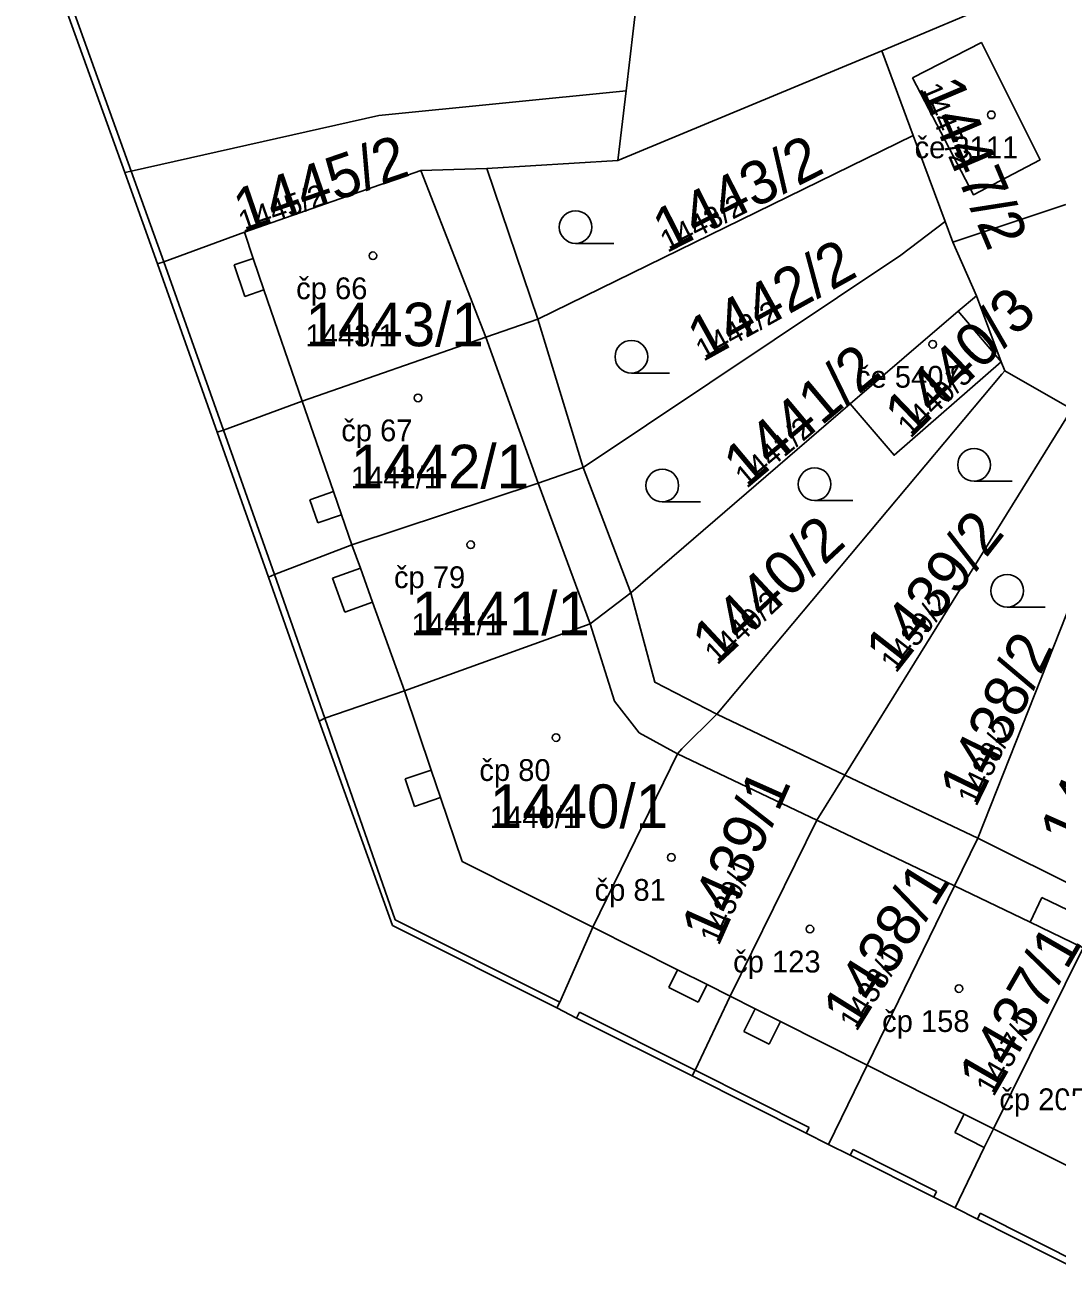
# Model space of a CAD drawing. Extents: x -763628 to -761565, y -976033 to -973833.
# Drawn here: x -762801.6 to -762754.2, y -975864.2 to -975806.8 of the extents above; entities that cross this region are included whole.
import ezdxf

# ---------------------------------------------------------------- set-up
doc = ezdxf.new("R2010")
doc.units = 0
for name, color, linetype in [('KN_cisla parcel 1000', 7, 'Continuous'), ('KN_cisla parcel 500', 7, 'Continuous'), ('KN_cisla popisna 500', 7, 'Continuous'), ('KN_hranice parcel', 7, 'Continuous'), ('KN_hranice uzemi', 7, 'Continuous'), ('KN_vnitrni kresba parcel', 7, 'Continuous'), ('KN_znacky budov', 7, 'Continuous'), ('KN_znacky kultur', 7, 'Continuous')]:
    doc.layers.add(name, color=color, linetype=linetype)

msp = doc.modelspace()

# ---------------------------------------------------------------- linework, layer by layer
at = {"layer": 'KN_hranice parcel'}
for p, q in [((-762774.01, -975809.85), (-762768.82, -975765.48)), ((-762762.28, -975808.02), (-762743.75, -975800.22)), ((-762762.28, -975808.02), (-762774.39, -975813.06)), ((-762760.84, -975811.91), (-762762.28, -975808.02)), ((-762774.39, -975813.06), (-762774.01, -975809.85)), ((-762760.84, -975811.91), (-762778.06, -975820.34)), ((-762759.37, -975815.85), (-762760.84, -975811.91)), ((-762774.39, -975813.06), (-762780.41, -975813.42)), ((-762778.06, -975820.34), (-762780.41, -975813.42)), ((-762759.02, -975816.8), (-762753.83, -975815.07)), ((-762759.02, -975816.8), (-762759.37, -975815.85)), ((-762757.93, -975819.27), (-762759.02, -975816.8)), ((-762756.79, -975822.3), (-762757.93, -975819.27)), ((-762775.98, -975827.14), (-762778.06, -975820.34)), ((-762756.63, -975822.71), (-762756.79, -975822.3)), ((-762753.55, -975824.46), (-762756.63, -975822.71)), ((-762763.73, -975824.23), (-762773.79, -975832.9)), ((-762753.55, -975824.46), (-762763.97, -975841.26)), ((-762757.87, -975844.15), (-762750.65, -975825.91)), ((-762773.79, -975832.9), (-762775.98, -975827.14)), ((-762763.97, -975841.26), (-762769.85, -975838.47)), ((-762757.87, -975844.15), (-762763.97, -975841.26)), ((-762752.01, -975847.08), (-762757.87, -975844.15))]:
    msp.add_line(p, q, dxfattribs=at)
for points in [[(-762760.87, -975809.26), (-762758.07, -975814.63), (-762755.01, -975813.02), (-762757.7, -975807.64), (-762760.87, -975809.26)], [(-762797.02, -975813.61), (-762796.74, -975813.55), (-762785.37, -975810.99), (-762774.01, -975809.85)], [(-762780.41, -975813.42), (-762783.44, -975813.52), (-762791.54, -975816.34), (-762795.23, -975817.7), (-762795.52, -975817.8)], [(-762759.37, -975815.85), (-762761.41, -975817.4), (-762775.98, -975827.14)], [(-762757.93, -975819.27), (-762758.77, -975819.97), (-762763.73, -975824.23)], [(-762778.06, -975820.34), (-762780.45, -975821.16), (-762788.89, -975824.1), (-762792.5, -975825.43), (-762792.79, -975825.53)], [(-762756.63, -975822.71), (-762756.77, -975822.86), (-762769.85, -975838.47)], [(-762756.79, -975822.3), (-762761.71, -975826.58), (-762763.73, -975824.23)], [(-762775.98, -975827.14), (-762778.05, -975827.87), (-762786.6, -975830.7), (-762790.16, -975832.05), (-762790.43, -975832.18)], [(-762773.79, -975832.9), (-762775.67, -975834.32), (-762784.19, -975837.39), (-762787.84, -975838.65), (-762788.11, -975838.79)], [(-762769.85, -975838.47), (-762772.69, -975837), (-762773.79, -975832.9)], [(-762769.85, -975838.47), (-762771.46, -975840.06), (-762771.65, -975840.28), (-762775.54, -975848.24), (-762777.06, -975851.69), (-762777.2, -975851.95)], [(-762763.97, -975841.26), (-762765.26, -975843.33), (-762769.24, -975851.41), (-762770.85, -975854.8), (-762770.98, -975855.07)], [(-762757.87, -975844.15), (-762758.94, -975846.35), (-762762.95, -975854.57), (-762764.72, -975858.22)], [(-762752.01, -975847.08), (-762752.49, -975848.06), (-762753.03, -975849.19), (-762757.15, -975857.49), (-762757.58, -975858.35), (-762758.91, -975861.13)]]:
    msp.add_lwpolyline(points, dxfattribs=at)
at = {"layer": 'KN_hranice uzemi'}
for p, q in [((-762797.02, -975813.61), (-762801.61, -975800.86)), ((-762792.79, -975825.53), (-762795.52, -975817.8)), ((-762790.43, -975832.18), (-762792.79, -975825.53)), ((-762788.11, -975838.79), (-762790.43, -975832.18)), ((-762784.74, -975848.17), (-762788.11, -975838.79)), ((-762777.2, -975851.95), (-762784.74, -975848.17))]:
    msp.add_line(p, q, dxfattribs=at)
for points in [[(-762795.52, -975817.8), (-762796.87, -975814.04), (-762797.02, -975813.61)], [(-762770.98, -975855.07), (-762776.29, -975852.41), (-762777.2, -975851.95)], [(-762764.72, -975858.22), (-762765.75, -975857.7), (-762770.98, -975855.07)], [(-762758.91, -975861.13), (-762759.89, -975860.64), (-762763.73, -975858.71), (-762764.72, -975858.22)], [(-762752.88, -975864.16), (-762757.89, -975861.64), (-762758.91, -975861.13)]]:
    msp.add_lwpolyline(points, dxfattribs=at)
at = {"layer": 'KN_vnitrni kresba parcel'}
for p, q in [((-762801.33, -975800.76), (-762796.74, -975813.55)), ((-762796.74, -975813.55), (-762795.23, -975817.7)), ((-762783.44, -975813.52), (-762780.45, -975821.16)), ((-762791.54, -975816.34), (-762791.13, -975817.55)), ((-762791.13, -975817.55), (-762792, -975817.85)), ((-762791.13, -975817.55), (-762790.64, -975818.99)), ((-762795.23, -975817.7), (-762792.5, -975825.43)), ((-762792, -975817.85), (-762791.51, -975819.29)), ((-762791.51, -975819.29), (-762790.64, -975818.99)), ((-762790.64, -975818.99), (-762788.89, -975824.1)), ((-762758.77, -975819.97), (-762756.79, -975822.3)), ((-762780.45, -975821.16), (-762778.05, -975827.87)), ((-762788.89, -975824.1), (-762787.45, -975828.25)), ((-762792.5, -975825.43), (-762790.16, -975832.05)), ((-762778.05, -975827.87), (-762775.67, -975834.32)), ((-762787.45, -975828.25), (-762788.53, -975828.63)), ((-762787.45, -975828.25), (-762787.08, -975829.31)), ((-762788.53, -975828.63), (-762788.17, -975829.69)), ((-762788.17, -975829.69), (-762787.08, -975829.31)), ((-762787.08, -975829.31), (-762786.6, -975830.7)), ((-762786.6, -975830.7), (-762786.21, -975831.77)), ((-762786.21, -975831.77), (-762787.49, -975832.23)), ((-762786.21, -975831.77), (-762785.65, -975833.33)), ((-762790.16, -975832.05), (-762787.84, -975838.65)), ((-762787.49, -975832.23), (-762786.93, -975833.79)), ((-762786.93, -975833.79), (-762785.65, -975833.33)), ((-762785.65, -975833.33), (-762784.19, -975837.39)), ((-762775.67, -975834.32), (-762774.55, -975837.87)), ((-762784.19, -975837.39), (-762782.96, -975841.04)), ((-762774.55, -975837.87), (-762773.42, -975839.32)), ((-762784.61, -975847.9), (-762787.84, -975838.65)), ((-762773.42, -975839.32), (-762771.65, -975840.28)), ((-762771.65, -975840.28), (-762765.26, -975843.33)), ((-762782.96, -975841.04), (-762784.15, -975841.44)), ((-762782.96, -975841.04), (-762782.53, -975842.29)), ((-762784.15, -975841.44), (-762783.73, -975842.7)), ((-762783.73, -975842.7), (-762782.53, -975842.29)), ((-762782.53, -975842.29), (-762781.54, -975845.23)), ((-762765.26, -975843.33), (-762758.94, -975846.35)), ((-762781.54, -975845.23), (-762775.54, -975848.24)), ((-762758.94, -975846.35), (-762755.47, -975848.01)), ((-762754.93, -975846.88), (-762755.47, -975848.01)), ((-762752.49, -975848.06), (-762754.93, -975846.88)), ((-762777.06, -975851.69), (-762784.61, -975847.9)), ((-762755.47, -975848.01), (-762753.03, -975849.19)), ((-762775.54, -975848.24), (-762771.65, -975850.2)), ((-762771.65, -975850.2), (-762772.05, -975851.01)), ((-762771.65, -975850.2), (-762770.3, -975850.88)), ((-762770.7, -975851.68), (-762770.3, -975850.88)), ((-762770.3, -975850.88), (-762769.24, -975851.41)), ((-762772.05, -975851.01), (-762770.7, -975851.68)), ((-762769.24, -975851.41), (-762768.09, -975851.99)), ((-762768.09, -975851.99), (-762768.61, -975853.03)), ((-762768.09, -975851.99), (-762766.93, -975852.57)), ((-762776.29, -975852.41), (-762776.16, -975852.14)), ((-762776.16, -975852.14), (-762770.85, -975854.8)), ((-762767.45, -975853.61), (-762766.93, -975852.57)), ((-762766.93, -975852.57), (-762762.95, -975854.57)), ((-762768.61, -975853.03), (-762767.45, -975853.61)), ((-762770.85, -975854.8), (-762765.61, -975857.43)), ((-762762.95, -975854.57), (-762758.49, -975856.82)), ((-762758.49, -975856.82), (-762758.92, -975857.67)), ((-762758.49, -975856.82), (-762757.15, -975857.49)), ((-762765.61, -975857.43), (-762765.75, -975857.7)), ((-762758.92, -975857.67), (-762757.58, -975858.35)), ((-762757.15, -975857.49), (-762752.77, -975859.69)), ((-762763.73, -975858.71), (-762763.59, -975858.44)), ((-762763.59, -975858.44), (-762759.76, -975860.37)), ((-762759.76, -975860.37), (-762759.89, -975860.64)), ((-762757.89, -975861.64), (-762757.76, -975861.37)), ((-762757.76, -975861.37), (-762752.74, -975863.89))]:
    msp.add_line(p, q, dxfattribs=at)
at = {"layer": 'KN_znacky budov'}
for centre in [(-762757.247, -975810.959), (-762785.637, -975817.429), (-762759.937, -975821.489), (-762783.567, -975823.949), (-762781.147, -975830.689), (-762777.227, -975839.539), (-762771.937, -975845.039), (-762765.577, -975848.329), (-762758.737, -975851.059)]:
    msp.add_circle(centre, 0.175, dxfattribs=at)
at = {"layer": 'KN_znacky kultur'}
for p, q in [((-762776.333, -975816.86), (-762774.583, -975816.86)), ((-762773.773, -975822.81), (-762772.023, -975822.81)), ((-762758.043, -975827.77), (-762756.293, -975827.77)), ((-762772.353, -975828.72), (-762770.603, -975828.72)), ((-762765.363, -975828.66), (-762763.613, -975828.66)), ((-762756.523, -975833.55), (-762754.773, -975833.55))]:
    msp.add_line(p, q, dxfattribs=at)
for centre in [(-762776.333, -975816.11), (-762773.773, -975822.06), (-762758.043, -975827.02), (-762772.353, -975827.97), (-762765.363, -975827.91), (-762756.523, -975832.8)]:
    msp.add_circle(centre, 0.75, dxfattribs=at)

# ---------------------------------------------------------------- texts
at = {"layer": 'KN_cisla parcel 1000'}
for s, rotation, p in [('1447/2', 293, (-762760.556, -975809.754)), ('1445/2', 19, (-762791.593, -975816.383)), ('1443/2', 27, (-762772.114, -975817.297)), ('1442/2', 29, (-762770.457, -975822.293)), ('1440/3', 44, (-762760.957, -975825.825)), ('1441/2', 40, (-762768.473, -975828.131)), ('1440/2', 43, (-762769.83, -975836.241)), ('1439/2', 52, (-762761.62, -975836.613)), ('1438/2', 64, (-762757.936, -975842.742)), ('1437/2', 66, (-762753.283, -975844.695)), ('1439/1', 66, (-762769.753, -975849.115)), ('1438/1', 58, (-762763.429, -975853.06)), ('1437/1', 60, (-762757.143, -975856.055))]:
    msp.add_text(s, height=2, rotation=rotation, dxfattribs=at).set_placement(p)
for s, p in [('1443/1', (-762788.73, -975821.58)), ('1442/1', (-762786.65, -975828.1)), ('1441/1', (-762783.86, -975834.84)), ('1440/1', (-762780.27, -975843.69))]:
    msp.add_text(s, height=2, dxfattribs=at).set_placement(p)
at = {"layer": 'KN_cisla parcel 500'}
for s, rotation, p in [('1447/2', 293, (-762760.556, -975809.754)), ('1445/2', 19, (-762791.593, -975816.383)), ('1443/2', 27, (-762772.114, -975817.297)), ('1442/2', 29, (-762770.457, -975822.293)), ('1440/3', 44, (-762760.957, -975825.825)), ('1441/2', 40, (-762768.473, -975828.131)), ('1440/2', 43, (-762769.83, -975836.241)), ('1439/2', 52, (-762761.62, -975836.613)), ('1438/2', 64, (-762757.936, -975842.742)), ('1439/1', 66, (-762769.753, -975849.115)), ('1438/1', 58, (-762763.429, -975853.06)), ('1437/1', 60, (-762757.143, -975856.055))]:
    msp.add_text(s, height=1, rotation=rotation, dxfattribs=at).set_placement(p)
for s, p in [('1443/1', (-762788.73, -975821.58)), ('1442/1', (-762786.65, -975828.1)), ('1441/1', (-762783.86, -975834.84)), ('1440/1', (-762780.27, -975843.69))]:
    msp.add_text(s, height=1, dxfattribs=at).set_placement(p)
at = {"layer": 'KN_cisla popisna 500'}
for s, p in [('če 3111', (-762760.771, -975812.951)), ('čp 66', (-762789.161, -975819.421)), ('če 5407', (-762763.461, -975823.481)), ('čp 67', (-762787.091, -975825.941)), ('čp 79', (-762784.671, -975832.681)), ('čp 80', (-762780.751, -975841.531)), ('čp 81', (-762775.461, -975847.031)), ('čp 123', (-762769.101, -975850.321)), ('čp 158', (-762762.261, -975853.051)), ('čp 205', (-762756.881, -975856.641))]:
    msp.add_text(s, height=1, dxfattribs=at).set_placement(p)

doc.saveas('drawing.dxf')
